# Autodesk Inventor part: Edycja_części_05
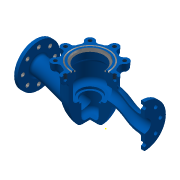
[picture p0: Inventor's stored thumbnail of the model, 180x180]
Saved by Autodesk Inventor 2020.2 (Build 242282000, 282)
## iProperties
Created: 2010-12
Part Number: Edycja_części_05
Document SubType Name: Modeling
Designer: F.Stasiak
Density: 7.1 g/cm^3
Material: Żeliwo sferoidalne
Appearance: Niebieski morski
Mass: 3462.48 g
Surface Area: 1171.68 cm^2
Volume: 487.674 cm^3
Manager: www.cadconsulting.pl
Company: Fabian Stasiak CAD Consulting
Author: F.Stasiak
Subject: Zbiór ćwiczeń. Autodesk Inventor 2020. Kurs podstawowy
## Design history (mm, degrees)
sketch "Szkic2"
  geometry: L1 (0, 0)-(0, 120); L2 (0, 120)-(50, 120); L3 (50, 120)-(50, 60); L4 (25, 0)-(0, 0); L5 (32.5, 120)-(32.5, 100); L6 (40, 50)-(0, 50); L7 (20, 50)-(20, 5); L8 (20, 5)-(0, 5); L9 (32.5, 100)-(40, 100); L10 (40, 100)-(40, 50); A1 r 84.5 centre (-34.5, 60) between (25, 0) and (50, 60)
  constraints: 20 end point, 7 perpendicular, 3 point on line, 2 parallel, 2 point on circle, 1 centre point, 1 midpoint, 1 tangent, 1 vertical
  dimensions: "d3" = 120 distance of L1.start L1.end; "d5" = 60 distance of L2.end L3.end; "d7" = 20 distance of L5.start L5.end; "d8" = 100 diameter of L3 L1; "d9" = 65 diameter of L5 L1; "d10" = 80 diameter of L10 L1; "d11" = 70 distance between parallel lines of L6 L2; "d12" = 40 diameter of L7 L1; "d13" = 50 diameter of L4.start L1; "d14" = 5 distance between parallel lines of L8 L4
revolve "Obrót1" sketch "Szkic2" stored, may be unused: angle "d15" = 90 deg
fillet "Zaokrąglenie1" dims "d20" = 10
fillet "Zaokrąglenie2" dims "d21" = 10
fillet "Zaokrąglenie3" dims "d22" = 15
node "Płaszczyzna konstrukcyjna1"
node "Płaszczyzna konstrukcyjna2"
sketch "Szkic3"
  geometry: C1 r 50 at (0, 50); 1 further point
  constraints: 1 centre point
  dimensions: "d25" = 100 diameter of C1; "d26" = 50 distance of point (0, 0) C1.centre
extrude "Wyciągnięcie proste2" join sketch "Szkic3" distance "d28" = 8; taper "d29" = 0 deg
node "Płaszczyzna konstrukcyjna3"
sketch "Szkic4"
  geometry: C1 r 20 at (0, 75); 1 further point
  constraints: 1 centre point, 1 vertical alignment
  dimensions: "d31" = 40 diameter of C1; "d32" = 75 distance of point (0, 0) C1.centre
sketch "Szkic5"
  geometry: C1 r 20 at (0, 0); 2 further points
  constraints: 2 horizontal alignment, 1 centre point, 1 other
  dimensions: "d33" = 40 diameter of C1
feature "Wyciągnięcie złożone1" sketch "Szkic4", "Szkic5" dims "d34" = 110, "d35" = 90 deg, "d36" = 110, "d37" = 90 deg
node "Płaszczyzna konstrukcyjna4"
sketch "Szkic7"
  geometry: 1 further point
sketch "Szkic8"
  geometry: C1 r 15 at (0, 75); 2 further points
  constraints: 1 centre point, 1 coincident
  dimensions: "d41" = 30 diameter of C1
sketch "Szkic9"
  geometry: C1 r 15 at (0, 0); 2 further points
  constraints: 1 centre point, 1 coincident, 1 horizontal alignment
  dimensions: "d42" = 30 diameter of C1
feature "Wyciągnięcie złożone2" sketch "Szkic9" dims "d43" = 160, "d44" = 90 deg, "d45" = 160, "d46" = 90 deg
sketch "Szkic10"
  geometry: 2 further points
  constraints: 1 vertical alignment
extrude "Wyciągnięcie proste3" join sketch "Szkic10" distance "d47" = 8; taper "d48" = 0 deg
node "Płaszczyzna konstrukcyjna6"
sketch "Szkic11"
  geometry: C1 r 20 at (0, 25); 1 further point
  constraints: 1 centre point, 1 vertical alignment
  dimensions: "d50" = 40 diameter of C1; "d51" = 25 distance of point (0, 0) C1.centre
sketch "Szkic12"
  geometry: C1 r 20 at (0, 0); 2 further points
  constraints: 1 centre point, 1 coincident, 1 horizontal alignment
  dimensions: "d52" = 40 diameter of C1
feature "Wyciągnięcie złożone3" sketch "Szkic11", "Szkic12" dims "d53" = 100, "d54" = 90 deg, "d55" = 100, "d56" = 90 deg
node "Płaszczyzna konstrukcyjna7"
sketch "Szkic13"
  geometry: C1 r 15 at (0, 25); 2 further points
  constraints: 1 centre point, 1 coincident
  dimensions: "d58" = 30 diameter of C1
sketch "Szkic14"
  geometry: C1 r 15 at (0, 0); 2 further points
  constraints: 1 centre point, 1 coincident, 1 horizontal alignment
  dimensions: "d59" = 30 diameter of C1
feature "Wyciągnięcie złożone4" sketch "Szkic13", "Szkic14" dims "d60" = 140, "d61" = 90 deg, "d62" = 140, "d63" = 90 deg
fillet "Zaokrąglenie4" dims "d64" = 5
fillet "Zaokrąglenie5" dims "d65" = 10
sketch "Szkic16"
  geometry: C1 r 32.5 at (0, 0) reference; C2 r 37.5 at (0, 0)
  constraints: 1 centre point
  dimensions: "d79" = 75 diameter of C2
extrude "Wyciągnięcie proste5" cut sketch "Szkic16" distance "d80" = 5; taper "d81" = 0 deg
sketch "Szkic17"
  geometry: C1 r 20 at (0, 0) reference; C2 r 25 at (0, 0)
  constraints: 1 centre point
  dimensions: "d82" = 50 diameter of C2
extrude "Wyciągnięcie proste6" cut sketch "Szkic17" distance "d83" = 5; taper "d84" = 0 deg
sketch "Szkic19" dims "d87" = 75
  geometry: 5 further points
  constraints: 3 horizontal alignment, 1 coincident, 2 other
hole "Hole2" sketch "Szkic19" at (37.5, 0) diameter "d88" = 9; stored, may be unused: countersink angle "d92" = 90 deg, drill point angle "d94" = 118 deg; dims "d89" = 6, "d90" = 4, "d91" = 2, "d93" = 8
pattern_circular "Szyk kołowy2" dims angle "d96" = 360 deg
mirror "Odbicie lustrzane2"
sketch "Szkic20" dims "d140" = 115 (= ŚREDNICA_PODZIAŁOWA)
  geometry: C1 r 50 at (0, 0) reference; C2 r 10 at (0, 57.5); C3 r 37.5 at (0, 0) reference; 1 further point
  constraints: 2 vertical alignment, 1 centre point, 1 coincident, 2 other
  dimensions: "d114" = 20 diameter of C2
extrude "Wyciągnięcie proste8" join sketch "Szkic20" distance "d98" = 20; taper "d99" = -5 deg
fillet "Zaokrąglenie6" dims "d100" = 8
fillet "Zaokrąglenie7" dims "d101" = 8
hole "Hole3" diameter "d104" = 8.376; stored, may be unused: countersink angle "d108" = 90 deg, drill point angle "d110" = 118 deg; dims "d102" = 10, "d103" = 10, "d105" = 6, "d106" = 4, "d107" = 2, "d109" = 12
pattern_circular "Szyk kołowy3" dims "d112" = 360 deg
sketch "Szkic24"
  geometry: C1 r 37.5 at (0, -57.5) reference; C2 r 45 at (0, -57.5); C3 r 42 at (0, -57.5)
  constraints: 2 centre point, 1 coincident
  dimensions: "d141" = 90 diameter of C2; "d142" = 3 radial gap between concentric circles of C2 C3
extrude "Wyciągnięcie proste12" cut sketch "Szkic24" distance "d143" = 3; taper "d144" = 0 deg
sketch "Szkic23"
  geometry: L1 (0, 0)-(128, 0); L2 (128, 0)-(128, -70); L3 (128, -70)-(0, -70); L4 (128, 50)-(128, -50) reference; L5 (0, 0)-(0, -70)
  constraints: 8 end point, 2 parallel, 1 collinear, 1 horizontal, 1 perpendicular
  dimensions: "d136" = 70 distance between parallel lines of L1 L3
extrude "Wyciągnięcie proste11" cut sketch "Szkic23" extent not by distance; stored distance "d137" = 30; taper "d138" = 0 deg
node "Bryła2"
other parameters: "d30" = 45, "d40" = -8, "d57" = 8, "ŚREDNICA_PODZIAŁOWA" = 115 [user parameter; used in 1 equation term]
